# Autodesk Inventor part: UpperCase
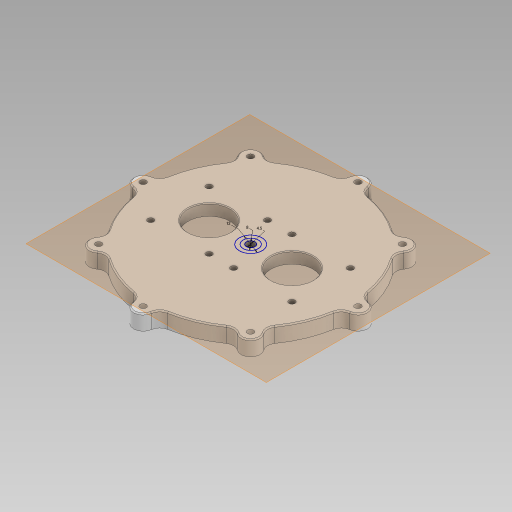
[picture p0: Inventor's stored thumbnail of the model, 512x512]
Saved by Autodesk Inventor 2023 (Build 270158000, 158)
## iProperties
Created: 2024-05
Part Number: UpperCase
Material: 一般
Document SubType Name: Modeling
Designer: kumagai
Density: 1 g/cm^3
Appearance: 既定
Author: kumagai
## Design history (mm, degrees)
derived "CoreSketch.ipt"
  sketch "Vertical"
    geometry: L1 (0, 65.337)-(0, -65.337) reference; L2 (-46.2, 0)-(46.2, 0) reference; L3 (-11, 2)-(11, 2) reference; L4 (11, 2)-(11, -2) reference; L5 (11, -2)-(-11, -2) reference; L6 (-11, -2)-(-11, 2) reference; L7 (11, 2)-(33, 2) reference; L8 (33, 2)-(33, -2) reference; L9 (33, -2)-(11, -2) reference; L10 (11, -2)-(11, 2) reference; L11 (22, 2.772)-(22, -2.683) reference; L12 (-33, 2)-(-11, 2) reference; L13 (-11, 2)-(-11, -2) reference; L14 (-11, -2)-(-33, -2) reference; L15 (-33, -2)-(-33, 2) reference; L16 (-22, 4.087)-(-22, -4.199) reference; L17 (-33, 10)-(-11, 10) reference; L18 (-11, 10)-(-11, 6) reference; L19 (-11, 6)-(-33, 6) reference; L20 (-33, 6)-(-33, 10) reference; L21 (-27.353, 10)-(-16.647, 10) reference; L22 (-16.647, 10)-(-16.647, 16) reference; L23 (-16.647, 16)-(-27.353, 16) reference; L24 (-27.353, 16)-(-27.353, 10) reference; L25 (11, 16)-(33, 16) reference; L26 (33, 16)-(33, 12) reference; L27 (33, 12)-(11, 12) reference; L28 (11, 12)-(11, 16) reference; L29 (16.134, 12)-(27.866, 12) reference; L30 (27.866, 12)-(27.866, 6) reference; L31 (27.866, 6)-(16.134, 6) reference; L32 (16.134, 6)-(16.134, 12) reference; L33 (-22, 18.272)-(-22, 9.031) reference; L34 (22, 22.635)-(22, 12.71) reference; L35 (33, -2)-(35, -2) reference; L36 (35, -2)-(35, 10) reference; L37 (35, 10)-(33, 10) reference; L38 (33, 10)-(33, -2) reference; L39 (0, -4)-(37.5, -4) reference; L40 (40.5, -1)-(40.5, 14) reference; L41 (43.9, -8)-(0, -8) reference; L42 (0, -4)-(0, -8) reference; L43 (35, -2)-(39, -2) reference; L44 (39, -2)-(39, 3.066) reference; L45 (38.45, 8.685)-(41.471, 10.429) reference; L46 (38.45, 10)-(35, 10) reference; L47 (40.5, 9.627)-(41.993, 8.375) reference; L48 (41.55, 3.315)-(40.5, 2.709) reference; L49 (37.5, -4)-(40.5, -1) reference; L50 (-43, 43.294)-(-1, 43.294) reference; L51 (-1, 43.294)-(-1, 26) reference; L52 (-1, 26)-(-43, 26) reference; L53 (-43, 26)-(-43, 43.294) reference; L54 (1, 43.294)-(43, 43.294) reference; L55 (43, 43.294)-(43, 26) reference; L56 (43, 26)-(1, 26) reference; L57 (1, 26)-(1, 43.294) reference; L58 (-22, 45.556)-(-22, 31.232) reference; L59 (22, 47.214)-(22, 32.287) reference; L60 (48, 5.268)-(48, -2.616) reference; L61 (43.6, -11)-(54, -11) reference; L62 (54, -11)-(54, 18) reference; L63 (45.222, -3.461)-(46.5, -2.566) reference; L64 (48, -2.616)-(49.192, -3.808) reference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; A1 r 3.1 centre (40, 6) between (39, 3.066) and (38.45, 8.685) reference; A2 r 3.1 centre (47, -6) between (45.222, -3.461) and (49.192, -3.808) reference; A3 r 3.1 centre (47, 13) between (43.9, 13) and (49, 10.631) reference; 2 further points; 1 other entity
    constraints: 1 other
  sketch "OuterLayout"
    geometry: L1 (0, -46.2)-(0, 46.2) reference; L2 (-73.4, 0)-(62.4, 0) reference; L3 (43, -21)-(1, -21) reference; L4 (1, -21)-(1, 21) reference; L5 (1, 21)-(43, 21) reference; L6 (43, 21)-(43, -21) reference; L7 (-1, -21)-(-43, -21) reference; L8 (-43, -21)-(-43, 21) reference; L9 (-43, 21)-(-1, 21) reference; L10 (-1, 21)-(-1, -21) reference; C1 r 11.1 at (22, 0) reference; C2 r 11.1 at (-22, 0) reference; C3 r 2.5 at (-22, 0) reference; C4 r 2.5 at (22, 0) reference; C5 r 1.6 at (-6.5, -15.5) reference; C6 r 1.6 at (-37.5, -15.5) reference; C7 r 1.6 at (-6.5, 15.5) reference; C8 r 1.6 at (-37.5, 15.5) reference; C9 r 51.5 at (0, 0) reference; C10 r 1.65 at (-57, 0) reference; A1 r 54 centre (0, 0) between (-53.229, -9.091) and (-53.229, 9.091) reference; A2 r 5 centre (-58.158, -9.933) between (-53.229, -9.091) and (-57.579, -4.966) reference; A3 r 5 centre (-58.158, 9.933) between (-57.579, 4.966) and (-53.229, 9.091) reference; A4 r 5 centre (-57, 0) between (-53.86, 3.891) and (-53.86, -3.891) reference; 1 further point
node "JointFace"
node "MotorFace"
sketch "スケッチ3"
  geometry: L1 (0, -75.6)-(0, 75.6) reference; L2 (-85.2, 0)-(77.2, 0) reference; L3 (-1, -21)-(-43, -21) reference; L4 (-1, 21)-(-1, -21) reference; L5 (-43, 21)-(-1, 21) reference; L6 (-43, -21)-(-43, 21) reference; C1 r 51.5 at (0, 0) reference; C2 r 1.65 at (-57, 0) reference; C3 r 11.1 at (-22, 0) reference; C4 r 1.6 at (-6.5, 15.5) reference; C5 r 1.6 at (-6.5, -15.5) reference; C6 r 1.6 at (-37.5, -15.5) reference; C7 r 1.6 at (-37.5, 15.5) reference; C8 r 46 at (0, 0); A1 r 54 centre (0, 0) between (-53.229, 9.091) and (-53.86, 3.891) reference; A2 r 5 centre (-58.158, 9.933) between (-57.579, 4.966) and (-53.229, 9.091) reference; A3 r 5 centre (-57, 0) between (-53.86, 3.891) and (-53.86, -3.891) reference; A4 r 5 centre (-58.158, -9.933) between (-53.229, -9.091) and (-57.579, -4.966) reference; 1 further point
  constraints: 1 centre point, 1 coincident
  dimensions: "d1" = 8 radial gap between concentric circles of A1 C8
extrude "押し出し1" new body sketch "スケッチ3" stored distance "d2" = 8; taper "d3" = 0 deg
extrude "押し出し2" join sketch "スケッチ3" stored distance "d5" = 10; taper "d6" = 0 deg
pattern_circular "円形状パターン1" dims angle "d8" = 360 deg
sketch "スケッチ4"
  geometry: L1 (50, -48.836)-(50, -5); L2 (50, -5)-(47.304, -5); L3 (16.696, -5)-(5.256, -5); L4 (16.696, 5)-(5.256, 5); L5 (47.304, 5)-(50, 5); L6 (50, 5)-(50, 48.836); L7 (54, -75.6)-(54, 75.6) reference; L8 (-31.2, 0)-(131.2, 0) reference; C1 r 1.6 at (47.5, -15.5) reference; C2 r 11.1 at (32, 0) reference; C3 r 1.6 at (47.5, 15.5) reference; C4 r 1.6 at (16.5, 15.5) reference; C5 r 54 at (54, 0) reference; C6 r 1.6 at (16.5, -15.5) reference; C7 r 4 at (47.5, -15.5); C8 r 4 at (16.5, -15.5); C9 r 4 at (16.5, 15.5); C10 r 4 at (47.5, 15.5); A1 r 49 centre (54, 0) between (50, -48.836) and (5.256, -5); A2 r 16.1 centre (32, 0) between (47.304, -5) and (16.696, -5); 7 further points
  constraints: 12 end point, 8 point on circle, 6 centre point, 6 coincident, 6 point on line, 3 equal radius, 1 other
  dimensions: "d10" = 5 radial gap between concentric circles of C5 A1; "d11" = 5 radial gap between concentric circles of A2 C2; "d12" = 4 distance between parallel lines of L7 L1; "d13" = 10 distance between parallel lines of L4 L3; "d14" = 8 diameter of C7
extrude "押し出し3" join sketch "スケッチ4" distance "d15" = 6; taper "d16" = 0 deg
extrude "押し出し4" join sketch "スケッチ4" distance "d17" = 2; taper "d18" = 0 deg
chamfer "面取り1" distance "d19" = 1.5; stored, may be unused: second distance "d20" = 2, angle "d21" = 45 deg
mirror "ミラー1"
chamfer "面取り2" distance "d22" = 0.6; stored, may be unused: second distance "d23" = 2, angle "d24" = 45 deg
chamfer "面取り4" distance "d37" = 0.4; stored, may be unused: second distance "d38" = 2, angle "d39" = 45 deg
sketch "スケッチ5"
  geometry: C1 r 4 at (54, 0); C2 r 6 at (54, 0); C3 r 2.25 at (54, 0); 1 further point
  constraints: 3 centre point, 3 coincident
  dimensions: "d25" = 8 diameter of C1; "d26" = 12 diameter of C2; "d31" = 4.5 diameter of C3
extrude "押し出し5" join sketch "スケッチ5" distance "d27" = 7; taper "d28" = 0 deg
extrude "押し出し6" cut sketch "スケッチ5" extent not by distance; stored distance "d29" = 0; taper "d30" = 0 deg
extrude "押し出し7" join sketch "スケッチ5" distance "d32" = 3; taper "d33" = 0 deg
node "ソリッド1"
other parameters: "d4" = 8
